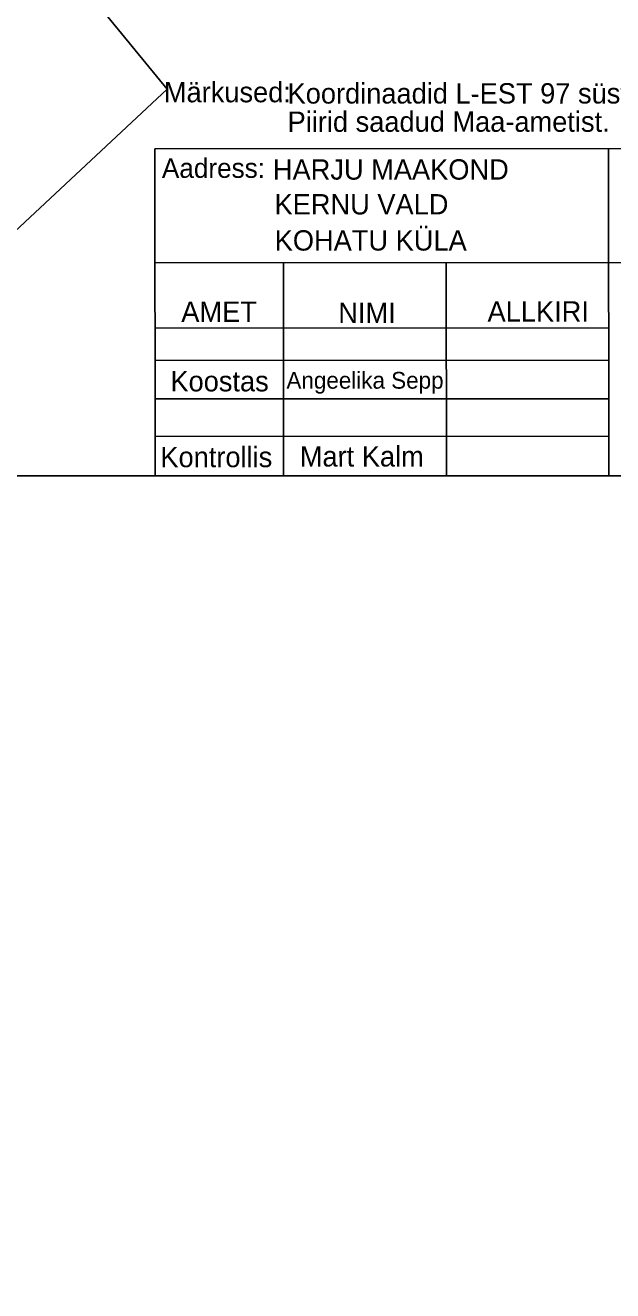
# Model space of a CAD drawing. Extents: x 529142 to 529430, y 6557605 to 6557874.
# Drawn here: x 529334.1 to 529370.2, y 6557604.8 to 6557682.6 of the extents above; entities that cross this region are included whole.
import ezdxf

# ---------------------------------------------------------------- set-up
doc = ezdxf.new("R2010")
doc.units = 0
doc.layers.add('PIIR', color=7, linetype='Continuous')
doc.layers.add('VORMISTUS', color=7, linetype='Continuous')

msp = doc.modelspace()

# ---------------------------------------------------------------- linework, layer by layer
at = {"layer": 'PIIR'}
msp.add_lwpolyline([(529141.76, 6557753.61), (529263.81, 6557604.78), (529342.84, 6557678.62), (529233.56, 6557811.89)], close=True, dxfattribs=at)
at = {"layer": 'VORMISTUS'}
msp.add_line((529360, 6557654.857), (529359.976, 6557667.954), dxfattribs=at)
msp.add_lwpolyline([(529239.596, 6557654.857), (529239.596, 6557793.357), (529429.596, 6557793.357), (529429.596, 6557654.857)], close=True, dxfattribs=at)
for points in [[(529342.084, 6557674.957), (529429.596, 6557674.977)], [(529342.106, 6557654.857), (529342.084, 6557674.957)], [(529369.966, 6557654.857), (529369.944, 6557674.964)], [(529342.086, 6557667.947), (529429.596, 6557667.977)], [(529349.986, 6557654.857), (529349.975, 6557667.95)], [(529342.096, 6557663.957), (529369.956, 6557663.947)], [(529342.096, 6557661.957), (529369.946, 6557661.967)], [(529342.096, 6557659.597), (529369.956, 6557659.597)], [(529342.106, 6557657.287), (529369.946, 6557657.297)]]:
    msp.add_lwpolyline(points, dxfattribs=at)

# ---------------------------------------------------------------- texts
for s, height, rotation, p in [('Märkused:', 1.25, 0.01064, (529342.635, 6557677.822)), ('Koordinaadid L-EST 97 süsteemis, kõrgused Balti süsteemis', 1.25, 0.01064, (529350.235, 6557677.744)), ('Piirid saadud Maa-ametist.', 1.25, 0.01064, (529350.235, 6557676.006)), ('Aadress:', 1.2, 0.01018, (529342.515, 6557673.178)), ('HARJU MAAKOND', 1.25, 0.01018, (529349.335, 6557673.068)), ('KERNU VALD', 1.25, 0.01018, (529349.435, 6557670.928)), ('KOHATU KÜLA', 1.25, 0.01018, (529349.445, 6557668.708)), ('AMET', 1.25, 0.01018, (529343.704, 6557664.325)), ('NIMI', 1.25, 0.01018, (529353.352, 6557664.253)), ('ALLKIRI', 1.25, 0.01018, (529362.521, 6557664.343)), ('Koostas', 1.25, 0.01018, (529343.037, 6557660.054)), ('Angeelika Sepp', 1.03052, 0.01018, (529350.166, 6557660.219)), ('Kontrollis', 1.25, 0.01018, (529342.42, 6557655.394)), ('Mart Kalm', 1.25, 0.01018, (529350.987, 6557655.434))]:
    msp.add_text(s, height=height, rotation=rotation, dxfattribs=at).set_placement(p)

doc.saveas('drawing.dxf')
